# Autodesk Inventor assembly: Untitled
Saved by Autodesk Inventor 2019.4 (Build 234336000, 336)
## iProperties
Created: 2020-01
Part Number: Untitled
Document SubType Name: Assembly
Designer: Administrator
Title: Untitled v9
Author: Administrator
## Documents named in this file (2)
- c:\worker\convert-fusion-r01\tmp\job-1\8\output\files\67a61d02-edeb-444f-99af-f8167cf0c0ad\9f8d66c7-0dd2-4305-bb10-b1325f224c04.iam
- c:\worker\convert-fusion-r01\tmp\job-1\8\output\files\67a61d02-edeb-444f-99af-f8167cf0c0ad\Untitled v9.ipt
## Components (1 placed, 1 different names)
1. Untitled v9
